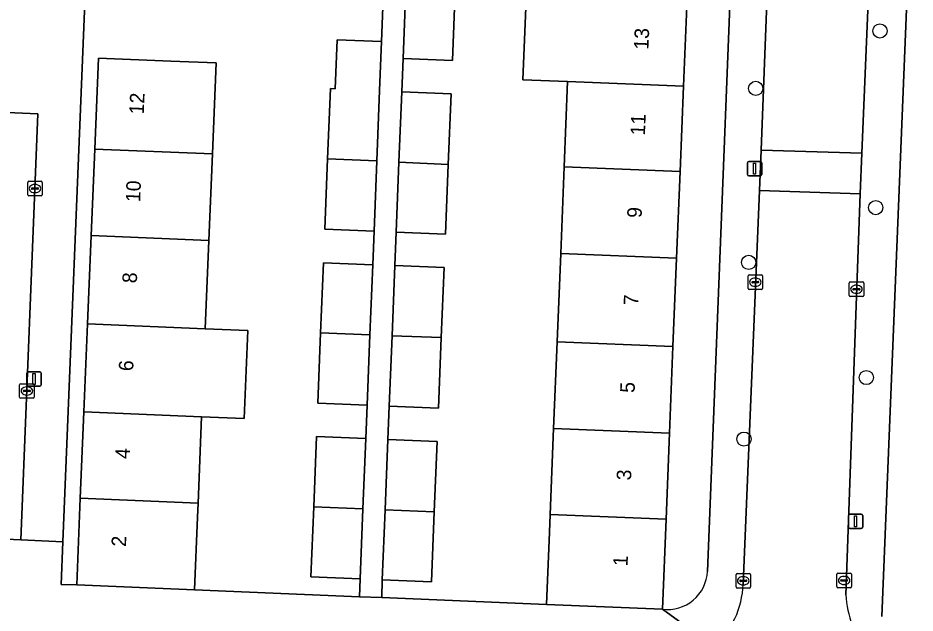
# Model space of a CAD drawing. Extents: x 161354 to 162026, y 386504 to 387460.
# Drawn here: x 161581.1 to 161642.9, y 387052.3 to 387093.4 of the extents above; entities that cross this region are included whole.
import ezdxf

# ---------------------------------------------------------------- set-up
doc = ezdxf.new("R2010")
doc.units = 0
for name, color, linetype in [('IMGEO_Boom', 7, 'Continuous'), ('IMGEO_Erf', 7, 'Continuous'), ('IMGEO_Groenvoorziening', 7, 'Continuous'), ('IMGEO_Kolk', 7, 'Continuous'), ('IMGEO_Lichtmast', 7, 'Continuous'), ('IMGEO_Muur', 7, 'Continuous'), ('IMGEO_Pand', 7, 'Continuous'), ('IMGEO_Pand_nummerreeks', 7, 'Continuous'), ('IMGEO_Rijbaan_lokaal_open', 7, 'Continuous'), ('IMGEO_Voetpad_open', 7, 'Continuous')]:
    doc.layers.add(name, color=color, linetype=linetype)

msp = doc.modelspace()

# ---------------------------------------------------------------- linework, layer by layer
at = {"layer": 'IMGEO_Boom'}
for centre in [(161640.512, 387092.491), (161631.944, 387088.529), (161640.221, 387080.308), (161631.459, 387076.526), (161639.571, 387068.585), (161631.137, 387064.342)]:
    msp.add_circle(centre, 0.489, dxfattribs=at)
at = {"layer": 'IMGEO_Erf'}
for points in [[(161628.95, 387119.868), (161608.808, 387120.684), (161608.768, 387119.62), (161611.806, 387119.498), (161614.843, 387119.375), (161617.88, 387119.253), (161620.918, 387119.131), (161623.956, 387119.008), (161626.993, 387118.886), (161626.756, 387112.985), (161627.941, 387112.937), (161627.692, 387106.761), (161627.449, 387100.706), (161627.21, 387094.781), (161626.964, 387088.676), (161626.728, 387082.8), (161626.487, 387076.815), (161626.241, 387070.719), (161626.001, 387064.761), (161625.762, 387058.813), (161625.512, 387052.604)], [(161628.619, 387055.213), (161631.069, 387117.573)], [(161585.719, 387095.031), (161584.181, 387057.259), (161584.061, 387054.307), (161585.131, 387054.287), (161585.377, 387060.264), (161585.622, 387066.214), (161585.872, 387072.281), (161586.123, 387078.382), (161586.368, 387084.34), (161586.627, 387090.62), (161591.623, 387090.415), (161594.747, 387090.286), (161594.488, 387084.006), (161594.243, 387078.048), (161593.992, 387071.947), (161596.924, 387071.826), (161596.674, 387065.759), (161593.742, 387065.88), (161593.497, 387059.93), (161593.457, 387058.949), (161593.251, 387053.953), (161604.624, 387053.472), (161604.673, 387054.697), (161601.275, 387054.832), (161601.468, 387059.668), (161601.661, 387064.515), (161605.059, 387064.379), (161605.15, 387066.682), (161601.753, 387066.817), (161601.946, 387071.663), (161602.139, 387076.5), (161605.536, 387076.365), (161605.629, 387078.685), (161602.232, 387078.82), (161602.425, 387083.666), (161602.618, 387088.513), (161602.95, 387088.499), (161603.084, 387091.884), (161606.15, 387091.762), (161606.225, 387094.128)], [(161611.226, 387095.296), (161611.032, 387090.454), (161607.635, 387090.591), (161607.542, 387088.289), (161610.94, 387088.153), (161610.744, 387083.275), (161610.551, 387078.476), (161607.154, 387078.612), (161607.062, 387076.306), (161610.459, 387076.17), (161610.265, 387071.34), (161610.07, 387066.478), (161606.673, 387066.615), (161606.581, 387064.322), (161609.978, 387064.186), (161609.783, 387059.336), (161609.589, 387054.489), (161606.191, 387054.626), (161606.16, 387053.406), (161617.522, 387052.925), (161617.723, 387057.921), (161617.772, 387059.135), (161618.011, 387065.083), (161618.251, 387071.041), (161618.497, 387077.137), (161618.738, 387083.122), (161618.974, 387088.998), (161615.889, 387089.122), (161616.135, 387095.227)]]:
    msp.add_lwpolyline(points, dxfattribs=at)
msp.add_arc((161625.857, 387055.348), 2.766, 262.84115, 357.20033, dxfattribs=at)
at = {"layer": 'IMGEO_Groenvoorziening'}
msp.add_lwpolyline([(161581.277, 387057.391), (161582.455, 387086.771), (161570.329, 387087.3), (161569.151, 387057.942)], close=True, dxfattribs=at)
at = {"layer": 'IMGEO_Kolk'}
for p, q in [((161581.749, 387081.193), (161581.749, 387082.045)), ((161581.824, 387082.119), (161582.676, 387082.119)), ((161582.75, 387082.045), (161582.75, 387081.193)), ((161582.008, 387081.613), (161582.008, 387081.625)), ((161582.446, 387081.576), (161582.048, 387081.576)), ((161582.051, 387081.662), (161582.449, 387081.662)), ((161582.237, 387081.899), (161582.262, 387081.899)), ((161582.492, 387081.625), (161582.492, 387081.613)), ((161582.676, 387081.119), (161581.824, 387081.119)), ((161582.26, 387081.339), (161582.235, 387081.339)), ((161631.417, 387074.738), (161631.417, 387075.59)), ((161631.492, 387075.664), (161632.344, 387075.664)), ((161631.719, 387075.207), (161632.117, 387075.207)), ((161631.905, 387075.444), (161631.93, 387075.444)), ((161632.418, 387075.59), (161632.418, 387074.738)), ((161632.344, 387074.664), (161631.492, 387074.664)), ((161631.676, 387075.158), (161631.676, 387075.17)), ((161632.114, 387075.121), (161631.716, 387075.121)), ((161631.928, 387074.884), (161631.903, 387074.884)), ((161632.16, 387075.17), (161632.16, 387075.158)), ((161638.391, 387074.25), (161638.391, 387075.102)), ((161638.466, 387075.176), (161639.318, 387075.176)), ((161638.65, 387074.67), (161638.65, 387074.682)), ((161639.088, 387074.633), (161638.69, 387074.633)), ((161638.693, 387074.719), (161639.091, 387074.719)), ((161638.879, 387074.956), (161638.904, 387074.956)), ((161639.134, 387074.682), (161639.134, 387074.67)), ((161639.392, 387075.102), (161639.392, 387074.25)), ((161639.318, 387074.176), (161638.466, 387074.176)), ((161638.902, 387074.396), (161638.877, 387074.396)), ((161581.189, 387067.236), (161581.189, 387068.088)), ((161581.264, 387068.162), (161582.116, 387068.162)), ((161581.677, 387067.942), (161581.702, 387067.942)), ((161582.19, 387068.088), (161582.19, 387067.236)), ((161582.116, 387067.162), (161581.264, 387067.162)), ((161581.448, 387067.656), (161581.448, 387067.668)), ((161581.886, 387067.619), (161581.488, 387067.619)), ((161581.491, 387067.705), (161581.889, 387067.705)), ((161581.7, 387067.382), (161581.675, 387067.382)), ((161581.932, 387067.668), (161581.932, 387067.656)), ((161630.587, 387054.144), (161630.587, 387054.996)), ((161630.662, 387055.07), (161631.514, 387055.07)), ((161631.075, 387054.85), (161631.1, 387054.85)), ((161631.588, 387054.996), (161631.588, 387054.144)), ((161637.542, 387054.167), (161637.542, 387055.019)), ((161637.617, 387055.093), (161638.469, 387055.093)), ((161638.03, 387054.873), (161638.055, 387054.873)), ((161638.543, 387055.019), (161638.543, 387054.167)), ((161630.846, 387054.564), (161630.846, 387054.576)), ((161631.284, 387054.527), (161630.886, 387054.527)), ((161630.889, 387054.613), (161631.287, 387054.613)), ((161631.098, 387054.29), (161631.073, 387054.29)), ((161631.33, 387054.576), (161631.33, 387054.564)), ((161637.801, 387054.587), (161637.801, 387054.599)), ((161638.239, 387054.55), (161637.841, 387054.55)), ((161637.844, 387054.636), (161638.242, 387054.636)), ((161638.053, 387054.313), (161638.028, 387054.313)), ((161638.285, 387054.599), (161638.285, 387054.587)), ((161631.514, 387054.07), (161630.662, 387054.07)), ((161638.469, 387054.093), (161637.617, 387054.093))]:
    msp.add_line(p, q, dxfattribs=at)
for points in [[(161581.749, 387081.193), (161581.749, 387082.045)], [(161581.824, 387082.119), (161582.676, 387082.119)], [(161582.75, 387082.045), (161582.75, 387081.193)], [(161582.676, 387081.119), (161581.824, 387081.119)], [(161631.417, 387074.738), (161631.417, 387075.59)], [(161631.492, 387075.664), (161632.344, 387075.664)], [(161632.418, 387075.59), (161632.418, 387074.738)], [(161632.344, 387074.664), (161631.492, 387074.664)], [(161638.391, 387074.25), (161638.391, 387075.102)], [(161638.466, 387075.176), (161639.318, 387075.176)], [(161639.392, 387075.102), (161639.392, 387074.25)], [(161639.318, 387074.176), (161638.466, 387074.176)], [(161581.189, 387067.236), (161581.189, 387068.088)], [(161581.264, 387068.162), (161582.116, 387068.162)], [(161582.19, 387068.088), (161582.19, 387067.236)], [(161582.116, 387067.162), (161581.264, 387067.162)], [(161630.587, 387054.144), (161630.587, 387054.996)], [(161630.662, 387055.07), (161631.514, 387055.07)], [(161631.588, 387054.996), (161631.588, 387054.144)], [(161637.542, 387054.167), (161637.542, 387055.019)], [(161637.617, 387055.093), (161638.469, 387055.093)], [(161638.543, 387055.019), (161638.543, 387054.167)], [(161631.514, 387054.07), (161630.662, 387054.07)], [(161638.469, 387054.093), (161637.617, 387054.093)]]:
    msp.add_lwpolyline(points, dxfattribs=at)
for centre, radius, start, end in [((161581.826, 387082.043), 0.0765, 91.55205, 178.44795), ((161581.826, 387082.043), 0.0765, 91.55205, 178.44795), ((161582.674, 387082.043), 0.0765, 1.55205, 88.44795), ((161582.674, 387082.043), 0.0765, 1.55205, 88.44795), ((161582.048, 387081.622), 0.0403, 85.87752, 175.75265), ((161582.045, 387081.612), 0.0366, 178.93798, 274.71019), ((161582.449, 387081.619), 0.043, 264.86636, 352.45326), ((161582.453, 387081.624), 0.0386, 1.73085, 96.63898), ((161581.826, 387081.195), 0.0765, 181.55205, 268.44795), ((161581.826, 387081.195), 0.0765, 181.55205, 268.44795), ((161582.674, 387081.195), 0.0765, 271.55205, 358.44795), ((161582.674, 387081.195), 0.0765, 271.55205, 358.44795), ((161631.494, 387075.588), 0.0765, 91.55205, 178.44795), ((161631.494, 387075.588), 0.0765, 91.55205, 178.44795), ((161631.716, 387075.167), 0.0403, 85.87752, 175.75265), ((161632.121, 387075.169), 0.0386, 1.73085, 96.63898), ((161632.342, 387075.588), 0.0765, 1.55205, 88.44795), ((161632.342, 387075.588), 0.0765, 1.55205, 88.44795), ((161631.494, 387074.74), 0.0765, 181.55205, 268.44795), ((161631.494, 387074.74), 0.0765, 181.55205, 268.44795), ((161631.713, 387075.157), 0.0366, 178.93798, 274.71019), ((161632.117, 387075.164), 0.043, 264.86636, 352.45326), ((161632.342, 387074.74), 0.0765, 271.55205, 358.44795), ((161632.342, 387074.74), 0.0765, 271.55205, 358.44795), ((161638.468, 387075.1), 0.0765, 91.55205, 178.44795), ((161638.468, 387075.1), 0.0765, 91.55205, 178.44795), ((161638.69, 387074.679), 0.0403, 85.87752, 175.75265), ((161638.687, 387074.669), 0.0366, 178.93798, 274.71019), ((161639.091, 387074.676), 0.043, 264.86636, 352.45326), ((161639.095, 387074.681), 0.0386, 1.73085, 96.63898), ((161639.316, 387075.1), 0.0765, 1.55205, 88.44795), ((161639.316, 387075.1), 0.0765, 1.55205, 88.44795), ((161638.468, 387074.252), 0.0765, 181.55205, 268.44795), ((161638.468, 387074.252), 0.0765, 181.55205, 268.44795), ((161639.316, 387074.252), 0.0765, 271.55205, 358.44795), ((161639.316, 387074.252), 0.0765, 271.55205, 358.44795), ((161581.266, 387068.086), 0.0765, 91.55205, 178.44795), ((161581.266, 387068.086), 0.0765, 91.55205, 178.44795), ((161582.114, 387068.086), 0.0765, 1.55205, 88.44795), ((161582.114, 387068.086), 0.0765, 1.55205, 88.44795), ((161581.266, 387067.238), 0.0765, 181.55205, 268.44795), ((161581.266, 387067.238), 0.0765, 181.55205, 268.44795), ((161581.488, 387067.665), 0.0403, 85.87752, 175.75265), ((161581.485, 387067.655), 0.0366, 178.93798, 274.71019), ((161581.889, 387067.662), 0.043, 264.86636, 352.45326), ((161581.893, 387067.667), 0.0386, 1.73085, 96.63898), ((161582.114, 387067.238), 0.0765, 271.55205, 358.44795), ((161582.114, 387067.238), 0.0765, 271.55205, 358.44795), ((161630.664, 387054.994), 0.0765, 91.55205, 178.44795), ((161630.664, 387054.994), 0.0765, 91.55205, 178.44795), ((161631.512, 387054.994), 0.0765, 1.55205, 88.44795), ((161631.512, 387054.994), 0.0765, 1.55205, 88.44795), ((161637.619, 387055.017), 0.0765, 91.55205, 178.44795), ((161637.619, 387055.017), 0.0765, 91.55205, 178.44795), ((161638.467, 387055.017), 0.0765, 1.55205, 88.44795), ((161638.467, 387055.017), 0.0765, 1.55205, 88.44795), ((161630.886, 387054.573), 0.0403, 85.87752, 175.75265), ((161630.883, 387054.563), 0.0366, 178.93798, 274.71019), ((161631.287, 387054.57), 0.043, 264.86636, 352.45326), ((161631.291, 387054.575), 0.0386, 1.73085, 96.63898), ((161637.619, 387054.169), 0.0765, 181.55205, 268.44795), ((161637.619, 387054.169), 0.0765, 181.55205, 268.44795), ((161637.841, 387054.596), 0.0403, 85.87752, 175.75265), ((161637.838, 387054.586), 0.0366, 178.93798, 274.71019), ((161638.242, 387054.593), 0.043, 264.86636, 352.45326), ((161638.246, 387054.598), 0.0386, 1.73085, 96.63898), ((161638.467, 387054.169), 0.0765, 271.55205, 358.44795), ((161638.467, 387054.169), 0.0765, 271.55205, 358.44795), ((161630.664, 387054.146), 0.0765, 181.55205, 268.44795), ((161630.664, 387054.146), 0.0765, 181.55205, 268.44795), ((161631.512, 387054.146), 0.0765, 271.55205, 358.44795), ((161631.512, 387054.146), 0.0765, 271.55205, 358.44795)]:
    msp.add_arc(centre, radius, start, end, dxfattribs=at)
for centre, major_axis, ratio, start_param, end_param in [((161582.236, 387081.619), (-0.387, 0.002), 0.722429, 4.712389, 7.853982), ((161582.261, 387081.619), (-0.39, 0.002), 0.717154, 1.570796, 4.712389), ((161631.904, 387075.164), (-0.387, 0.002), 0.722429, 4.712389, 7.853982), ((161631.929, 387075.164), (-0.39, 0.002), 0.717154, 1.570796, 4.712389), ((161638.878, 387074.676), (-0.387, 0.002), 0.722429, 4.712389, 7.853982), ((161638.903, 387074.676), (-0.39, 0.002), 0.717154, 1.570796, 4.712389), ((161581.676, 387067.662), (-0.387, 0.002), 0.722429, 4.712389, 7.853982), ((161581.701, 387067.662), (-0.39, 0.002), 0.717154, 1.570796, 4.712389), ((161631.074, 387054.57), (-0.387, 0.002), 0.722429, 4.712389, 7.853982), ((161631.099, 387054.57), (-0.39, 0.002), 0.717154, 1.570796, 4.712389), ((161638.029, 387054.593), (-0.387, 0.002), 0.722429, 4.712389, 7.853982), ((161638.054, 387054.593), (-0.39, 0.002), 0.717154, 1.570796, 4.712389)]:
    msp.add_ellipse(centre, major_axis=major_axis, ratio=ratio, start_param=start_param, end_param=end_param, dxfattribs=at)
at = {"layer": 'IMGEO_Lichtmast'}
for p, q in [((161631.37, 387082.594), (161631.37, 387083.394)), ((161631.37, 387083.394), (161631.37, 387082.594)), ((161631.47, 387083.494), (161632.26, 387083.494)), ((161632.26, 387083.494), (161631.47, 387083.494)), ((161632.36, 387083.394), (161632.36, 387082.594)), ((161632.36, 387082.594), (161632.36, 387083.394)), ((161632.26, 387082.494), (161631.47, 387082.494)), ((161631.47, 387082.494), (161632.26, 387082.494)), ((161581.692, 387068.083), (161581.692, 387068.883)), ((161581.692, 387068.883), (161581.692, 387068.083)), ((161581.792, 387068.983), (161582.582, 387068.983)), ((161582.582, 387068.983), (161581.792, 387068.983)), ((161582.682, 387068.883), (161582.682, 387068.083)), ((161582.682, 387068.083), (161582.682, 387068.883)), ((161582.582, 387067.983), (161581.792, 387067.983)), ((161581.792, 387067.983), (161582.582, 387067.983)), ((161638.433, 387059.169), (161639.223, 387059.169)), ((161639.223, 387059.169), (161638.433, 387059.169)), ((161638.333, 387058.269), (161638.333, 387059.069)), ((161638.333, 387059.069), (161638.333, 387058.269)), ((161639.323, 387059.069), (161639.323, 387058.269)), ((161639.323, 387058.269), (161639.323, 387059.069)), ((161639.223, 387058.169), (161638.433, 387058.169)), ((161638.433, 387058.169), (161639.223, 387058.169))]:
    msp.add_line(p, q, dxfattribs=at)
for points in [[(161631.79, 387083.369), (161631.94, 387083.369), (161631.94, 387082.619), (161631.79, 387082.619), (161631.79, 387083.369)], [(161582.112, 387068.858), (161582.262, 387068.858), (161582.262, 387068.108), (161582.112, 387068.108), (161582.112, 387068.858)], [(161638.753, 387059.044), (161638.903, 387059.044), (161638.903, 387058.294), (161638.753, 387058.294), (161638.753, 387059.044)]]:
    msp.add_lwpolyline(points, dxfattribs=at)
for centre, start, end in [((161631.47, 387083.394), 90, 180), ((161631.47, 387083.394), 90, 180), ((161632.26, 387083.394), 0, 90), ((161632.26, 387083.394), 360, 90), ((161631.47, 387082.594), 180, 270), ((161631.47, 387082.594), 180, 270), ((161632.26, 387082.594), 270, 0), ((161632.26, 387082.594), 270, 0), ((161581.792, 387068.883), 90, 180), ((161581.792, 387068.883), 90, 180), ((161582.582, 387068.883), 0, 90), ((161582.582, 387068.883), 360, 90), ((161581.792, 387068.083), 180, 270), ((161581.792, 387068.083), 180, 270), ((161582.582, 387068.083), 270, 0), ((161582.582, 387068.083), 270, 0), ((161638.433, 387059.069), 90, 180), ((161638.433, 387059.069), 90, 180), ((161639.223, 387059.069), 0, 90), ((161639.223, 387059.069), 360, 90), ((161638.433, 387058.269), 180, 270), ((161638.433, 387058.269), 180, 270), ((161639.223, 387058.269), 270, 0), ((161639.223, 387058.269), 270, 0)]:
    msp.add_arc(centre, 0.1, start, end, dxfattribs=at)
at = {"layer": 'IMGEO_Muur'}
for points in [[(161604.616, 387053.472), (161593.251, 387053.953)], [(161606.16, 387053.406), (161617.522, 387052.925)]]:
    msp.add_lwpolyline(points, dxfattribs=at)
at = {"layer": 'IMGEO_Pand'}
for points in [[(161611.226, 387095.296), (161607.829, 387095.432), (161607.635, 387090.591), (161611.032, 387090.454)], [(161627.21, 387094.781), (161619.22, 387095.103), (161616.135, 387095.227), (161615.889, 387089.122), (161618.974, 387088.998), (161626.964, 387088.676)], [(161606.015, 387088.377), (161606.15, 387091.762), (161603.084, 387091.884), (161602.95, 387088.499), (161602.618, 387088.513), (161602.425, 387083.666), (161605.822, 387083.531)], [(161594.488, 387084.006), (161594.747, 387090.286), (161591.623, 387090.415), (161586.627, 387090.62), (161586.368, 387084.34)], [(161618.974, 387088.998), (161618.738, 387083.122), (161626.728, 387082.8), (161626.964, 387088.676)], [(161607.542, 387088.289), (161607.348, 387083.443), (161610.744, 387083.275), (161610.94, 387088.153)], [(161594.243, 387078.048), (161594.488, 387084.006), (161586.368, 387084.34), (161586.123, 387078.382)], [(161605.822, 387083.531), (161602.425, 387083.666), (161602.232, 387078.82), (161605.629, 387078.685)], [(161610.744, 387083.275), (161607.348, 387083.443), (161607.154, 387078.612), (161610.551, 387078.476)], [(161618.738, 387083.122), (161618.497, 387077.137), (161626.487, 387076.815), (161626.728, 387082.8)], [(161586.123, 387078.382), (161585.872, 387072.281), (161593.992, 387071.947), (161594.243, 387078.048)], [(161618.497, 387077.137), (161618.251, 387071.041), (161626.241, 387070.719), (161626.487, 387076.815)], [(161605.536, 387076.365), (161602.139, 387076.5), (161601.946, 387071.663), (161605.344, 387071.528)], [(161607.062, 387076.306), (161606.867, 387071.46), (161610.265, 387071.34), (161610.459, 387076.17)], [(161596.924, 387071.826), (161593.992, 387071.947), (161585.872, 387072.281), (161585.622, 387066.214), (161593.742, 387065.88), (161596.674, 387065.759)], [(161605.344, 387071.528), (161601.946, 387071.663), (161601.753, 387066.817), (161605.15, 387066.682)], [(161610.265, 387071.34), (161606.867, 387071.46), (161606.673, 387066.615), (161610.07, 387066.478)], [(161626.001, 387064.761), (161626.241, 387070.719), (161618.251, 387071.041), (161618.011, 387065.083)], [(161585.622, 387066.214), (161585.377, 387060.264), (161593.497, 387059.93), (161593.742, 387065.88)], [(161618.011, 387065.083), (161617.772, 387059.135), (161625.762, 387058.813), (161626.001, 387064.761)], [(161605.059, 387064.379), (161601.661, 387064.515), (161601.468, 387059.668), (161604.866, 387059.533)], [(161606.581, 387064.322), (161606.386, 387059.472), (161609.783, 387059.336), (161609.978, 387064.186)], [(161593.251, 387053.953), (161593.457, 387058.949), (161593.497, 387059.93), (161585.377, 387060.264), (161585.131, 387054.287)], [(161604.866, 387059.533), (161601.468, 387059.668), (161601.275, 387054.832), (161604.673, 387054.697)], [(161609.783, 387059.336), (161606.386, 387059.472), (161606.191, 387054.626), (161609.589, 387054.489)], [(161625.512, 387052.604), (161625.762, 387058.813), (161617.772, 387059.135), (161617.723, 387057.921), (161617.522, 387052.925)]]:
    msp.add_lwpolyline(points, close=True, dxfattribs=at)
at = {"layer": 'IMGEO_Rijbaan_lokaal_open'}
for points in [[(161640.696, 387118.073), (161641.045, 387126.421), (161641.557, 387139.242), (161634.628, 387139.442), (161634.383, 387133.402), (161634.401, 387133.163), (161633.569, 387116.709), (161632.313, 387084.273), (161639.273, 387084.053)], [(161639.157, 387081.267), (161639.273, 387084.053), (161632.313, 387084.273), (161632.197, 387081.475)]]:
    msp.add_lwpolyline(points, close=True, dxfattribs=at)
for points in [[(161639.157, 387081.267), (161632.197, 387081.475), (161631.08, 387054.332)], [(161638.157, 387053.608), (161639.157, 387081.267)]]:
    msp.add_lwpolyline(points, dxfattribs=at)
for centre, radius, start, end in [((161624.878, 387054.583), 6.207, 312.68279, 357.6827), ((161644.697, 387053.924), 6.547, 182.76437, 220.32357)]:
    msp.add_arc(centre, radius, start, end, dxfattribs=at)
at = {"layer": 'IMGEO_Voetpad_open'}
for points in [[(161644.459, 387210.411), (161644.347, 387208.691), (161643.727, 387194.219), (161643.725, 387194.16), (161643.611, 387191.311), (161641.655, 387142.032), (161641.557, 387139.242), (161641.045, 387126.421), (161641.6, 387126.407), (161641.241, 387118.059), (161640.696, 387118.073), (161639.273, 387084.053), (161639.157, 387081.267), (161638.157, 387053.608)], [(161640.632, 387052.106), (161643.367, 387119.453), (161643.579, 387126.358), (161644.703, 387152.9)], [(161632.512, 387120.217), (161631.069, 387117.573), (161628.619, 387055.213)], [(161642.536, 387050.052), (161646.133, 387049.974), (161646.379, 387055.9), (161644.677, 387055.972), (161644.934, 387062.156), (161645.18, 387068.086), (161645.427, 387074.037), (161645.672, 387079.957), (161645.924, 387086.029), (161646.169, 387091.93), (161646.418, 387097.936), (161646.663, 387103.839), (161646.914, 387109.896), (161647.17, 387116.057), (161655.276, 387115.72), (161666.914, 387115.118), (161667.127, 387118.661), (161643.367, 387119.453), (161640.632, 387052.106)], [(161632.197, 387081.475), (161632.313, 387084.273), (161633.569, 387116.709)], [(161606.225, 387094.128), (161606.15, 387091.762), (161606.015, 387088.377), (161605.822, 387083.531), (161605.629, 387078.685), (161605.536, 387076.365), (161605.344, 387071.528), (161605.15, 387066.682), (161605.059, 387064.379), (161604.866, 387059.533), (161604.673, 387054.697), (161604.624, 387053.472), (161606.16, 387053.406), (161606.191, 387054.626), (161606.386, 387059.472), (161606.581, 387064.322), (161606.673, 387066.615), (161606.867, 387071.46), (161607.062, 387076.306), (161607.154, 387078.612), (161607.348, 387083.443), (161607.542, 387088.289), (161607.635, 387090.591), (161607.829, 387095.432)], [(161631.08, 387054.332), (161632.197, 387081.475)], [(161593.251, 387053.953), (161585.131, 387054.287), (161584.061, 387054.307), (161584.181, 387057.259), (161581.277, 387057.391), (161569.151, 387057.942), (161566.212, 387058.157), (161559.376, 387058.435), (161545.81, 387058.986), (161544.294, 387059.047), (161530.723, 387059.599), (161520.801, 387060.002), (161518.836, 387054.51)], [(161629.086, 387050.02), (161625.512, 387052.604), (161617.522, 387052.925), (161606.16, 387053.406), (161604.624, 387053.472), (161593.251, 387053.953)], [(161625.512, 387052.604), (161629.086, 387050.02)]]:
    msp.add_lwpolyline(points, dxfattribs=at)
msp.add_lwpolyline([(161585.719, 387095.031), (161585.787, 387096.692), (161567.776, 387097.249), (161567.726, 387096.004), (161566.212, 387058.157), (161569.151, 387057.942), (161570.329, 387087.3), (161582.455, 387086.771), (161581.277, 387057.391), (161584.181, 387057.259)], close=True, dxfattribs=at)
for centre, radius, start, end in [((161625.857, 387055.348), 2.766, 262.84115, 357.20033), ((161624.878, 387054.583), 6.207, 312.68279, 357.6827), ((161644.697, 387053.924), 6.547, 182.76437, 220.32357)]:
    msp.add_arc(centre, radius, start, end, dxfattribs=at)

# ---------------------------------------------------------------- texts
at = {"layer": 'IMGEO_Pand_nummerreeks'}
for s, rotation, p in [('13', 87.69692, (161624.543, 387091.186)), ('12', 87.6422, (161589.749, 387086.72)), ('11', 87.69452, (161624.304, 387085.268)), ('10', 87.6422, (161589.5, 387080.67)), ('9', 87.69452, (161624.076, 387079.581)), ('8', 87.6422, (161589.27, 387075.076)), ('7', 87.69452, (161623.833, 387073.547)), ('6', 87.63962, (161589.02, 387069.015)), ('5', 87.69452, (161623.591, 387067.514)), ('4', 87.6422, (161588.771, 387062.961)), ('3', 87.69452, (161623.348, 387061.481)), ('2', 87.6422, (161588.521, 387056.903)), ('1', 87.69452, (161623.109, 387055.561))]:
    msp.add_text(s, height=1, rotation=rotation, dxfattribs=at).set_placement(p)

doc.saveas('drawing.dxf')
